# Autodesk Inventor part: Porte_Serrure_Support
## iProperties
Created: 2009-01
Part Number: Porte_Serrure_Support
Document SubType Name: Modeling
Designer: claivier
Author: claivier
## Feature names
1. Base1
